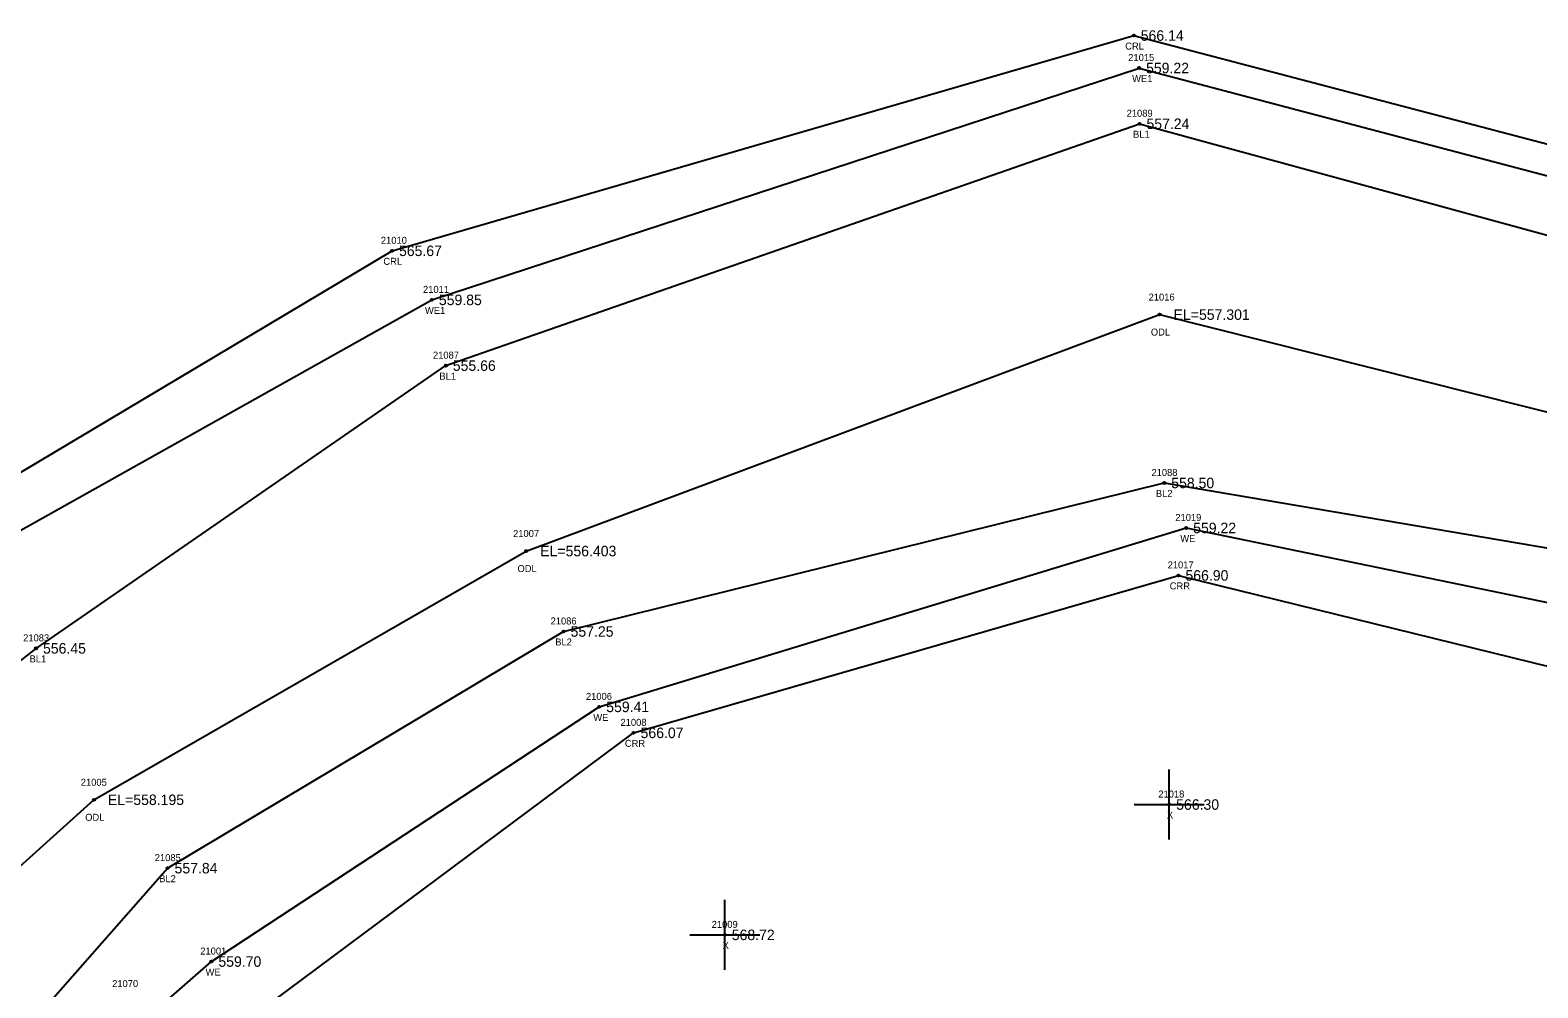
# Model space of a CAD drawing. Extents: x 1695443 to 1696344, y 1087542 to 1090645.
# Drawn here: x 1695877.6 to 1696093, y 1089047 to 1089183.8 of the extents above; entities that cross this region are included whole.
import ezdxf

# ---------------------------------------------------------------- set-up
doc = ezdxf.new("R2010")
doc.units = 0
for name, color, linetype in [('RD_DTM_BkLn1', 7, 'Continuous'), ('RD_DTM_BkLn_txCode', 7, 'Continuous'), ('RD_EX_H2O', 7, 'Continuous'), ('RD_EX_H2O_txCode', 7, 'Continuous'), ('RD_EX_Misc', 7, 'Continuous'), ('RD_EX_Misc_txCode', 7, 'Continuous'), ('RD_EX_TX_H2O_ELEV', 7, 'Continuous'), ('RD_EX_TX_Misc_ELEV', 7, 'Continuous'), ('RD_HC_Survey_txCode', 7, 'Continuous'), ('RD_SMD_Locator', 7, 'Continuous')]:
    doc.layers.add(name, color=color, linetype=linetype)

msp = doc.modelspace()

# ---------------------------------------------------------------- linework, layer by layer
at = {"layer": 'RD_DTM_BkLn1'}
for points in [[(1695477.93, 1088750.04), (1695615.7, 1088831.98), (1695678.81, 1088884.02), (1695727.39, 1088931.9), (1695787.9, 1089007.61), (1695838.8, 1089064.32), (1695878.44, 1089095.49), (1695937, 1089135.88), (1696036.12, 1089170.43), (1696157.88, 1089137.18), (1696204, 1089102.76), (1696222.69, 1089094.08), (1696233.22, 1089076.04), (1696249.95, 1089031.73), (1696253.49, 1088951.92)], [(1695519.05, 1088717.19), (1695621.07, 1088784.34), (1695706.03, 1088842.06), (1695754.64, 1088904.72), (1695822.43, 1088986.95), (1695872.19, 1089035.65), (1695897.24, 1089064.09), (1695953.83, 1089097.9), (1696039.66, 1089119.12), (1696131.31, 1089103.56), (1696189.39, 1089073.13), (1696217.04, 1089023.97), (1696212.37, 1088964.66)]]:
    msp.add_lwpolyline(points, dxfattribs=at)
at = {"layer": 'RD_EX_H2O'}
for points in [[(1695741.44, 1088979.77), (1695766.31, 1089008.66), (1695772.21, 1089014.13), (1695837.09, 1089090.39), (1695860.76, 1089111.44), (1695929.31, 1089152.28), (1696035.3, 1089183.03), (1696164.17, 1089149.21), (1696221.7, 1089111.38), (1696248.95, 1089080.06), (1696273.19, 1089047.83), (1696283.59, 1089011.28), (1696295.68, 1088944.39)], [(1695466.3, 1088756.42), (1695582.06, 1088826.6), (1695651.04, 1088873.87), (1695702.34, 1088921.12), (1695742.91, 1088967.28), (1695775.02, 1089011.92), (1695840.03, 1089086.93), (1695863.99, 1089105.53), (1695935.01, 1089145.27), (1696036.06, 1089178.39), (1696162.35, 1089145.09), (1696220.48, 1089108.56), (1696243.56, 1089079.86), (1696260.75, 1089035.89), (1696273.81, 1089006.71), (1696286.66, 1088942.65)], [(1695498.69, 1088725.6), (1695608.54, 1088797.54), (1695668.72, 1088841.78), (1695723.76, 1088906.07), (1695797.15, 1088991.78), (1695861.15, 1089050.89), (1695886.72, 1089073.86), (1695948.49, 1089109.39), (1696039, 1089143.17), (1696151.62, 1089114.84), (1696213.01, 1089073.69), (1696220.87, 1089032.47), (1696230.14, 1088992.72), (1696246.9, 1088917.69)], [(1695518.5, 1088708.22), (1695626.45, 1088775.86), (1695695.79, 1088824.57), (1695753.51, 1088889.68), (1695821.81, 1088964.67), (1695880.24, 1089030.4), (1695903.5, 1089050.75), (1695958.92, 1089087.13), (1696042.79, 1089112.69), (1696142.64, 1089092.08), (1696193.08, 1089060.79), (1696207.36, 1089030.79), (1696205.38, 1088967.18), (1696218.5, 1088901.4)], [(1695520.92, 1088704.05), (1695627.53, 1088770.84), (1695697.51, 1088817.15), (1695757.08, 1088884.85), (1695828.4, 1088961.5), (1695887.69, 1089025.09), (1695910.13, 1089043.49), (1695963.83, 1089083.42), (1696041.69, 1089105.91), (1696137.07, 1089082.48), (1696174.24, 1089034.61), (1696185.76, 1089011.54), (1696200.45, 1088973.14), (1696214.06, 1088899.28)]]:
    msp.add_lwpolyline(points, dxfattribs=at)
at = {"layer": 'RD_EX_Misc'}
for p, q in [((1696040.36, 1089068.18), (1696040.36, 1089078.18)), ((1696035.36, 1089073.18), (1696045.36, 1089073.18)), ((1695976.86, 1089049.56), (1695976.86, 1089059.56)), ((1695971.86, 1089054.56), (1695981.86, 1089054.56))]:
    msp.add_line(p, q, dxfattribs=at)
at = {"layer": 'RD_SMD_Locator'}
for centre in [(1696035.3, 1089183.03), (1696036.06, 1089178.39), (1696036.12, 1089170.43), (1695929.31, 1089152.28), (1695935.01, 1089145.27), (1696039, 1089143.17), (1695937, 1089135.88), (1696039.66, 1089119.12), (1696042.79, 1089112.69), (1695948.49, 1089109.39), (1696041.69, 1089105.91), (1695953.83, 1089097.9), (1695878.44, 1089095.49), (1695958.92, 1089087.13), (1695963.83, 1089083.42), (1695886.72, 1089073.86), (1696040.36, 1089073.18), (1695897.24, 1089064.09), (1695976.86, 1089054.56), (1695903.5, 1089050.75)]:
    msp.add_circle(centre, 0.15, dxfattribs=at)

# ---------------------------------------------------------------- texts
at = {"layer": 'RD_DTM_BkLn_txCode'}
for s, p in [('21089', (1696034.28, 1089171.43)), ('BL1', (1696035.2, 1089168.43)), ('21087', (1695935.16, 1089136.88)), ('BL1', (1695936.08, 1089133.88)), ('21088', (1696037.83, 1089120.12)), ('BL2', (1696038.46, 1089117.12)), ('21086', (1695951.97, 1089098.9)), ('21083', (1695876.6, 1089096.49)), ('BL2', (1695952.63, 1089095.9)), ('BL1', (1695877.52, 1089093.49)), ('21085', (1695895.41, 1089065.09)), ('BL2', (1695896.04, 1089062.09))]:
    msp.add_text(s, height=1, dxfattribs=at).set_placement(p)
at = {"layer": 'RD_EX_H2O_txCode'}
for s, p in [('CRL', (1696034.08, 1089181.03)), ('21015', (1696034.51, 1089179.39)), ('WE1', (1696035.07, 1089176.39)), ('21010', (1695927.72, 1089153.28)), ('CRL', (1695928.08, 1089150.28)), ('21011', (1695933.74, 1089146.27)), ('21016', (1696037.42, 1089145.17)), ('WE1', (1695934.02, 1089143.27)), ('ODL', (1696037.75, 1089140.17)), ('21019', (1696041.24, 1089113.69)), ('21007', (1695946.61, 1089111.39)), ('WE', (1696041.95, 1089110.69)), ('ODL', (1695947.24, 1089106.39)), ('21017', (1696040.14, 1089106.91)), ('CRR', (1696040.44, 1089103.91)), ('21006', (1695957.02, 1089088.13)), ('WE', (1695958.08, 1089085.13)), ('21008', (1695961.96, 1089084.42)), ('CRR', (1695962.58, 1089081.42)), ('21005', (1695884.84, 1089075.86)), ('ODL', (1695885.47, 1089070.86)), ('21001', (1695901.91, 1089051.75)), ('WE', (1695902.67, 1089048.75))]:
    msp.add_text(s, height=1, dxfattribs=at).set_placement(p)
at = {"layer": 'RD_EX_Misc_txCode'}
for s, p in [('21018', (1696038.81, 1089074.18)), ('X', (1696040.04, 1089071.18)), ('21009', (1695974.99, 1089055.56)), ('X', (1695976.55, 1089052.56))]:
    msp.add_text(s, height=1, dxfattribs=at).set_placement(p)
at = {"layer": 'RD_EX_TX_H2O_ELEV'}
for s, p in [('566.14', (1696036.3, 1089182.28)), ('559.22', (1696037.06, 1089177.64)), ('565.67', (1695930.31, 1089151.53)), ('559.85', (1695936.01, 1089144.52)), ('EL=557.301', (1696041, 1089142.42)), ('559.22', (1696043.79, 1089111.94)), ('EL=556.403', (1695950.49, 1089108.64)), ('566.90', (1696042.69, 1089105.16)), ('559.41', (1695959.92, 1089086.38)), ('566.07', (1695964.83, 1089082.67)), ('EL=558.195', (1695888.72, 1089073.11)), ('559.70', (1695904.5, 1089050))]:
    msp.add_text(s, height=1.5, dxfattribs=at).set_placement(p)
at = {"layer": 'RD_EX_TX_Misc_ELEV'}
for s, p in [('557.24', (1696037.12, 1089169.68)), ('555.66', (1695938, 1089135.13)), ('558.50', (1696040.66, 1089118.37)), ('557.25', (1695954.83, 1089097.15)), ('556.45', (1695879.44, 1089094.74)), ('566.30', (1696041.36, 1089072.43)), ('557.84', (1695898.24, 1089063.34)), ('568.72', (1695977.86, 1089053.81))]:
    msp.add_text(s, height=1.5, dxfattribs=at).set_placement(p)
at = {"layer": 'RD_HC_Survey_txCode'}
msp.add_text('21070', height=1, dxfattribs=at).set_placement((1695889.32, 1089047.1))

doc.saveas('drawing.dxf')
